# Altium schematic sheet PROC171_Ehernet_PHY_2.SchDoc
size 431 x 279 mm; Date: Not shown in title block; ApprovedBy: Not shown in title block; CheckedBy: Not shown in title block; Author: Not shown in title block; CompanyName: Not shown in title block; Engineer: Not shown in title block; Organization: Not shown in title block; Address1: Not shown in title block; Address2: Not shown in title block; Address3: Not shown in title block; Address4: Not shown in title block; DocumentNumber: 18; Revision: Use project parameter SCH_Rev; SheetNumber: 18; SheetTotal: 27; PageSetup: Record=PageOptions¦CenterHorizontal=True¦CenterVertical=True¦PrintScale=1.00¦XCorrection=1.00¦YCorrection=1.00¦PrintKind=0¦BorderSize=5000000¦LeftOffset=0¦BottomOffset=0¦Orientation=2¦PaperLength=1000¦PaperWidth=1000¦Scale=100¦PaperSource=15¦PrintQuality=600¦MediaType=1¦DitherType=10¦PaperKind=Letter¦PrintScaleMode=1
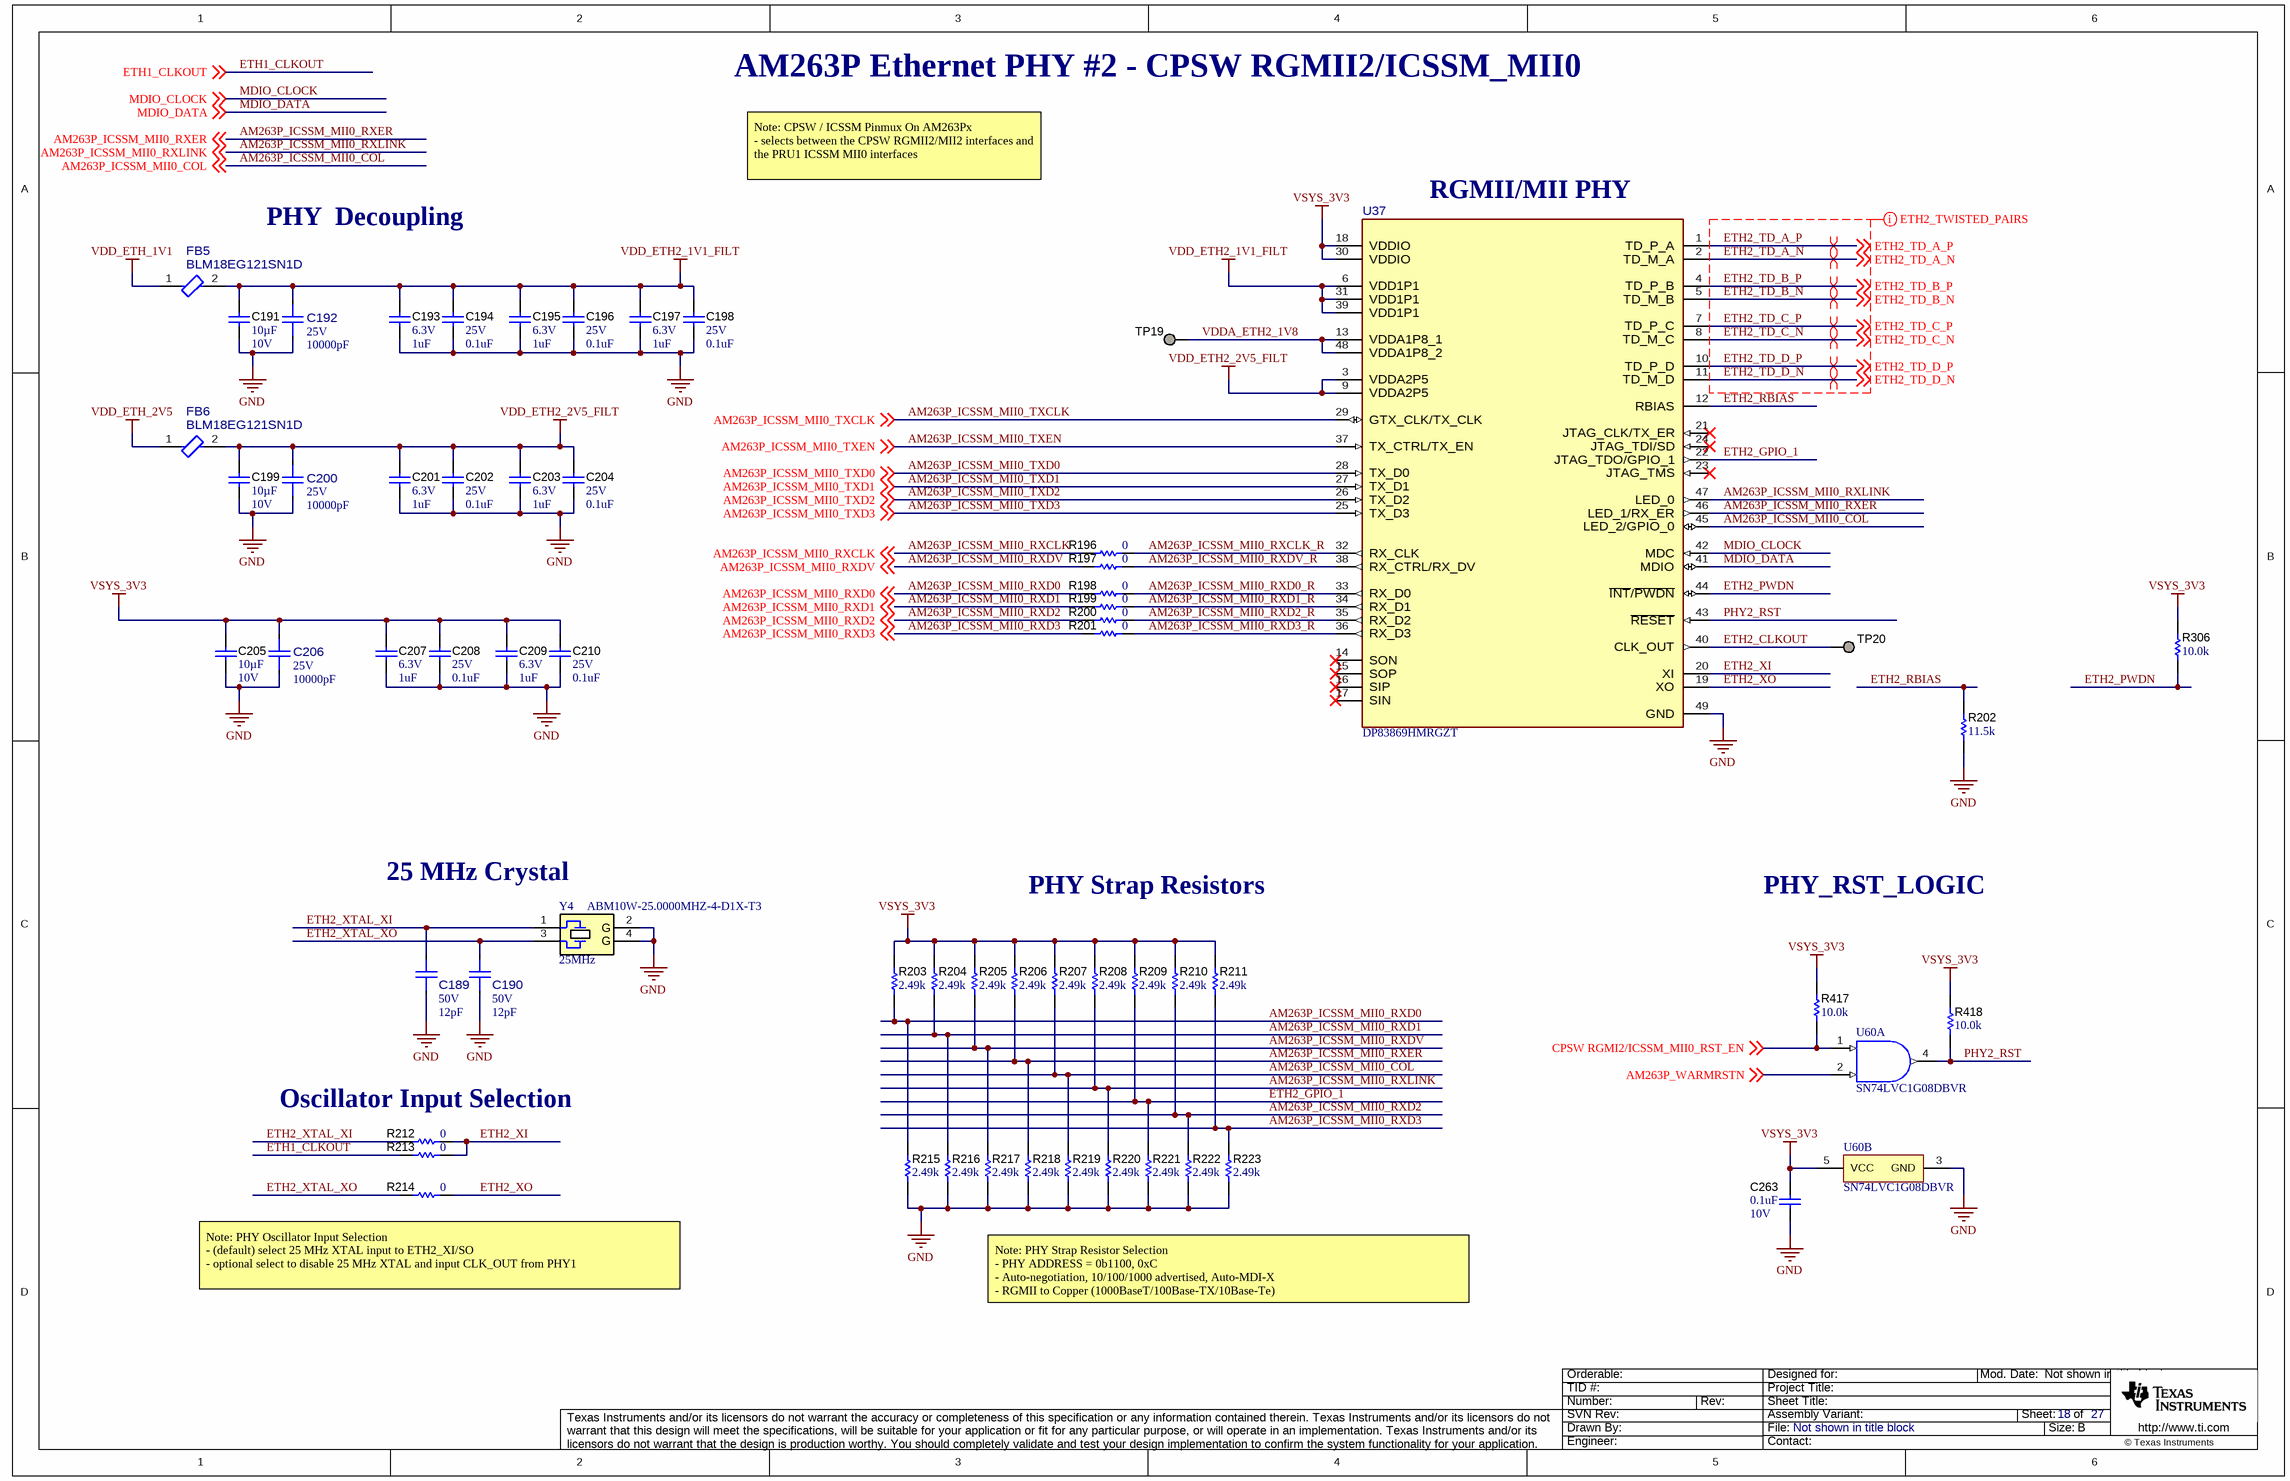
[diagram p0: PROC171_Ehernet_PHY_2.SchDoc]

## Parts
C189  VDC_V: 50V  ValueDisplayed: 12pF  [FP-GJM1555C1H120JB01D_0402-MFG]  (hidden comment: GJM1555C1H120JB01D)
C190  VDC_V: 50V  ValueDisplayed: 12pF  [FP-GJM1555C1H120JB01D_0402-MFG]  (hidden comment: GJM1555C1H120JB01D)
C191  Cap_F: 10µF  VDC_V: 10V  [0603]  (hidden comment: GRM188Z71A106MA73D)
C192  VDC_V: 25V  ValueDisplayed: 10000pF  [FP-GRM1555C1E103JE01D_0402-MFG]  (hidden comment: GRM1555C1E103JE01D)
C193  VDC_V: 6.3V  ValueDisplayed: 1uF  [0402]  (hidden comment: GRM155R70J105MA12D)
C194  VDC_V: 25V  ValueDisplayed: 0.1uF  [0402]  (hidden comment: GRM155R71E104KE14D)
C195  VDC_V: 6.3V  ValueDisplayed: 1uF  [0402]  (hidden comment: GRM155R70J105MA12D)
C196  VDC_V: 25V  ValueDisplayed: 0.1uF  [0402]  (hidden comment: GRM155R71E104KE14D)
C197  VDC_V: 6.3V  ValueDisplayed: 1uF  [0402]  (hidden comment: GRM155R70J105MA12D)
C198  VDC_V: 25V  ValueDisplayed: 0.1uF  [0402]  (hidden comment: GRM155R71E104KE14D)
C199  Cap_F: 10µF  VDC_V: 10V  [0603]  (hidden comment: GRM188Z71A106MA73D)
C200  VDC_V: 25V  ValueDisplayed: 10000pF  [FP-GRM1555C1E103JE01D_0402-MFG]  (hidden comment: GRM1555C1E103JE01D)
C201  VDC_V: 6.3V  ValueDisplayed: 1uF  [0402]  (hidden comment: GRM155R70J105MA12D)
C202  VDC_V: 25V  ValueDisplayed: 0.1uF  [0402]  (hidden comment: GRM155R71E104KE14D)
C203  VDC_V: 6.3V  ValueDisplayed: 1uF  [0402]  (hidden comment: GRM155R70J105MA12D)
C204  VDC_V: 25V  ValueDisplayed: 0.1uF  [0402]  (hidden comment: GRM155R71E104KE14D)
C205  Cap_F: 10µF  VDC_V: 10V  [0603]  (hidden comment: GRM188Z71A106MA73D)
C206  VDC_V: 25V  ValueDisplayed: 10000pF  [FP-GRM1555C1E103JE01D_0402-MFG]  (hidden comment: GRM1555C1E103JE01D)
C207  VDC_V: 6.3V  ValueDisplayed: 1uF  [0402]  (hidden comment: GRM155R70J105MA12D)
C208  VDC_V: 25V  ValueDisplayed: 0.1uF  [0402]  (hidden comment: GRM155R71E104KE14D)
C209  VDC_V: 6.3V  ValueDisplayed: 1uF  [0402]  (hidden comment: GRM155R70J105MA12D)
C210  VDC_V: 25V  ValueDisplayed: 0.1uF  [0402]  (hidden comment: GRM155R71E104KE14D)
C263  VDC_V: 10V  ValueDisplayed: 0.1uF  [0402]  (hidden comment: 885012105010)
FB5  BLM18EG121SN1D  [FP-BLM18EG121SN1D_0603-MFG]
FB6  BLM18EG121SN1D  [FP-BLM18EG121SN1D_0603-MFG]
R196  ValueDisplayed: 0  [0402]  (hidden comment: ERJ-2GE0R00X)
R197  ValueDisplayed: 0  [0402]  (hidden comment: ERJ-2GE0R00X)
R198  ValueDisplayed: 0  [0402]  (hidden comment: ERJ-2GE0R00X)
R199  ValueDisplayed: 0  [0402]  (hidden comment: ERJ-2GE0R00X)
R200  ValueDisplayed: 0  [0402]  (hidden comment: ERJ-2GE0R00X)
R201  ValueDisplayed: 0  [0402]  (hidden comment: ERJ-2GE0R00X)
R202  ValueDisplayed: 11.5k  [0402]  (hidden comment: ERJ-2RKF1152X)
R203  ValueDisplayed: 2.49k  [0402]  (hidden comment: CRCW04022K49FKED)
R204  ValueDisplayed: 2.49k  [0402]  (hidden comment: CRCW04022K49FKED)
R205  ValueDisplayed: 2.49k  [0402]  (hidden comment: CRCW04022K49FKED)
R206  ValueDisplayed: 2.49k  [0402]  (hidden comment: CRCW04022K49FKED)
R207  ValueDisplayed: 2.49k  [0402]  (hidden comment: CRCW04022K49FKED)
R208  ValueDisplayed: 2.49k  [0402]  (hidden comment: CRCW04022K49FKED)
R209  ValueDisplayed: 2.49k  [0402]  (hidden comment: CRCW04022K49FKED)
R210  ValueDisplayed: 2.49k  [0402]  (hidden comment: CRCW04022K49FKED)
R211  ValueDisplayed: 2.49k  [0402]  (hidden comment: CRCW04022K49FKED)
R212  ValueDisplayed: 0  [0402]  (hidden comment: ERJ-2GE0R00X)
R213  ValueDisplayed: 0  [0402]  (hidden comment: ERJ-2GE0R00X)
R214  ValueDisplayed: 0  [0402]  (hidden comment: ERJ-2GE0R00X)
R215  ValueDisplayed: 2.49k  [0402]  (hidden comment: CRCW04022K49FKED)
R216  ValueDisplayed: 2.49k  [0402]  (hidden comment: CRCW04022K49FKED)
R217  ValueDisplayed: 2.49k  [0402]  (hidden comment: CRCW04022K49FKED)
R218  ValueDisplayed: 2.49k  [0402]  (hidden comment: CRCW04022K49FKED)
R219  ValueDisplayed: 2.49k  [0402]  (hidden comment: CRCW04022K49FKED)
R220  ValueDisplayed: 2.49k  [0402]  (hidden comment: CRCW04022K49FKED)
R221  ValueDisplayed: 2.49k  [0402]  (hidden comment: CRCW04022K49FKED)
R222  ValueDisplayed: 2.49k  [0402]  (hidden comment: CRCW04022K49FKED)
R223  ValueDisplayed: 2.49k  [0402]  (hidden comment: CRCW04022K49FKED)
R306  ValueDisplayed: 10.0k  [0402]  (hidden comment: ERJ-2RKF1002X)
R417  ValueDisplayed: 10.0k  [0402]  (hidden comment: ERJ-2RKF1002X)
R418  ValueDisplayed: 10.0k  [0402L]  (hidden comment: CRCW040210K0FKED)
TP19  TESTPOINT  [TP_25MIL-SMT]  (value not drawn)  (no BOM)
TP20  TESTPOINT  [TP_25MIL-SMT]  (value not drawn)  (no BOM)
U37  DP83869HMRGZT  [RGZ0048B-MFG]
U60  SN74LVC1G08DBVR  [DBV0005A_N]  (parts A,B of 2)
Y4  Frequency_Fixed: 25MHz  [Abracon_ABM10W]  (hidden comment: ABM10W-25.0000MHZ-4-D1X-T3)

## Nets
GND: C189.1 C190.1 C191.2 C192.1 C193.2 C194.2 C195.2 C196.2 C197.2 C198.2 C199.2 C200.1 C201.2 C202.2 C203.2 C204.2 C205.2 C206.1 C207.2 C208.2 C209.2 C210.2 C263.2 R202.1 R215.1 R216.1 R217.1 R218.1 R219.1 R220.1 R221.1 R222.1 R223.1 U37.49(GND) U60.3(GND) Y4.2(GND) Y4.4(GND)
VDD_ETH2_1V1_FILT: C191.1 C192.2 C193.1 C194.1 C195.1 C196.1 C197.1 C198.1 FB5.2 U37.6(VDD1P1) U37.31(VDD1P1) U37.39(VDD1P1)
VDD_ETH2_2V5_FILT: C199.1 C200.2 C201.1 C202.1 C203.1 C204.1 FB6.2 U37.3(VDDA2P5) U37.9(VDDA2P5)
VDD_ETH_1V1: FB5.1
VDD_ETH_2V5: FB6.1
VSYS_3V3: C205.1 C206.2 C207.1 C208.1 C209.1 C210.1 C263.1 R203.2 R204.2 R205.2 R206.2 R207.2 R208.2 R209.2 R210.2 R211.2 R306.1 R417.1 R418.2 U37.18(VDDIO) U37.30(VDDIO) U60.5(VCC)
AM263P_ICSSM_MII0_COL: R207.1 R219.2 U37.45(LED_2/GPIO_0) ; off-sheet AM263P_ICSSM_MII0_COL
AM263P_ICSSM_MII0_RXCLK: R196.1 ; off-sheet AM263P_ICSSM_MII0_RXCLK
AM263P_ICSSM_MII0_RXCLK_R: R196.2 U37.32(RX_CLK)
AM263P_ICSSM_MII0_RXD0: R198.1 R203.1 R215.2 ; off-sheet AM263P_ICSSM_MII0_RXD0
AM263P_ICSSM_MII0_RXD0_R: R198.2 U37.33(RX_D0)
AM263P_ICSSM_MII0_RXD1: R199.1 R204.1 R216.2 ; off-sheet AM263P_ICSSM_MII0_RXD1
AM263P_ICSSM_MII0_RXD1_R: R199.2 U37.34(RX_D1)
AM263P_ICSSM_MII0_RXD2: R200.1 R210.1 R222.2 ; off-sheet AM263P_ICSSM_MII0_RXD2
AM263P_ICSSM_MII0_RXD2_R: R200.2 U37.35(RX_D2)
AM263P_ICSSM_MII0_RXD3: R201.1 R211.1 R223.2 ; off-sheet AM263P_ICSSM_MII0_RXD3
AM263P_ICSSM_MII0_RXD3_R: R201.2 U37.36(RX_D3)
AM263P_ICSSM_MII0_RXDV: R197.1 R205.1 R217.2 ; off-sheet AM263P_ICSSM_MII0_RXDV
AM263P_ICSSM_MII0_RXDV_R: R197.2 U37.38(RX_CTRL/RX_DV)
AM263P_ICSSM_MII0_RXER: R206.1 R218.2 U37.46(LED_1/RX_ER) ; off-sheet AM263P_ICSSM_MII0_RXER
AM263P_ICSSM_MII0_RXLINK: R208.1 R220.2 U37.47(LED_0) ; off-sheet AM263P_ICSSM_MII0_RXLINK
AM263P_ICSSM_MII0_TXCLK: U37.29(GTX_CLK/TX_CLK) ; off-sheet AM263P_ICSSM_MII0_TXCLK
AM263P_ICSSM_MII0_TXD0: U37.28(TX_D0) ; off-sheet AM263P_ICSSM_MII0_TXD0
AM263P_ICSSM_MII0_TXD1: U37.27(TX_D1) ; off-sheet AM263P_ICSSM_MII0_TXD1
AM263P_ICSSM_MII0_TXD2: U37.26(TX_D2) ; off-sheet AM263P_ICSSM_MII0_TXD2
AM263P_ICSSM_MII0_TXD3: U37.25(TX_D3) ; off-sheet AM263P_ICSSM_MII0_TXD3
AM263P_ICSSM_MII0_TXEN: U37.37(TX_CTRL/TX_EN) ; off-sheet AM263P_ICSSM_MII0_TXEN
AM263P_WARMRSTN: U60.2(B) ; off-sheet AM263P_WARMRSTN
CPSW RGMI2/ICSSM_MII0_RST_EN: R417.2 U60.1(A) ; off-sheet CPSW RGMI2/ICSSM_MII0_RST_EN
ETH1_CLKOUT: R213.1 ; off-sheet ETH1_CLKOUT
ETH2_CLKOUT: TP20.1 U37.40(CLK_OUT)
ETH2_GPIO_1: R209.1 R221.2 U37.22(JTAG_TDO/GPIO_1)
ETH2_PWDN: R306.2 U37.44(~{INT}/~{PWDN})
ETH2_RBIAS: R202.2 U37.12(RBIAS)
ETH2_TD_A_N: U37.2(TD_M_A) ; off-sheet ETH2_TD_A_N
ETH2_TD_A_P: U37.1(TD_P_A) ; off-sheet ETH2_TD_A_P
ETH2_TD_B_N: U37.5(TD_M_B) ; off-sheet ETH2_TD_B_N
ETH2_TD_B_P: U37.4(TD_P_B) ; off-sheet ETH2_TD_B_P
ETH2_TD_C_N: U37.8(TD_M_C) ; off-sheet ETH2_TD_C_N
ETH2_TD_C_P: U37.7(TD_P_C) ; off-sheet ETH2_TD_C_P
ETH2_TD_D_N: U37.11(TD_M_D) ; off-sheet ETH2_TD_D_N
ETH2_TD_D_P: U37.10(TD_P_D) ; off-sheet ETH2_TD_D_P
ETH2_XI: R212.2 R213.2 U37.20(XI)
ETH2_XO: R214.2 U37.19(XO)
ETH2_XTAL_XI: C189.2 R212.1 Y4.1
ETH2_XTAL_XO: C190.2 R214.1 Y4.3
MDIO_CLOCK: U37.42(MDC) ; off-sheet MDIO_CLOCK
MDIO_DATA: U37.41(MDIO) ; off-sheet MDIO_DATA
PHY2_RST: R418.1 U37.43(~{RESET}) U60.4(Y)
VDDA_ETH2_1V8: TP19.1 U37.13(VDDA1P8_1) U37.48(VDDA1P8_2)

Not connected (* = marked no-connect by the designer): U37 14(SON)* 15(SOP)* 16(SIP)* 17(SIN)* 21(JTAG_CLK/TX_ER)* 23(JTAG_TMS)* 24(JTAG_TDI/SD)*

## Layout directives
differential pair: ETH2_TD_A_N, ETH2_TD_A_P, ETH2_TD_B_N, ETH2_TD_B_P, ETH2_TD_C_N, ETH2_TD_C_P, ETH2_TD_D_N, ETH2_TD_D_P
mark named ETH2_TWISTED_PAIRS: ETH2_TD_A_N, ETH2_TD_A_P, ETH2_TD_B_N, ETH2_TD_B_P, ETH2_TD_C_N, ETH2_TD_C_P, ETH2_TD_D_N, ETH2_TD_D_P

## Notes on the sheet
- AM263P Ethernet PHY #2 - CPSW RGMII2/ICSSM_MII0
- PHY  Decoupling
- Note: CPSW / ICSSM Pinmux On AM263Px
  - selects between the CPSW RGMII2/MII2 interfaces and the PRU1 ICSSM MII0 interfaces
- (near U37) RGMII/MII PHY
- (near Y4) 25 MHz Crystal
- PHY Strap Resistors
- PHY_RST_LOGIC
- Oscillator Input Selection
- (near R214) Note: PHY Oscillator Input Selection
  - (default) select 25 MHz XTAL input to ETH2_XI/SO
  - optional select to disable 25 MHz XTAL and input CLK_OUT from PHY1
- Note: PHY Strap Resistor Selection
  - PHY ADDRESS = 0b1100, 0xC
  - Auto-negotiation, 10/100/1000 advertised, Auto-MDI-X
  - RGMII to Copper (1000BaseT/100Base-TX/10Base-Te)

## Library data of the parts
C189 C190 = CMP-0035228-1: Multi-Layer Ceramic Capacitor 12pF C0G  ±5% 0402 Paper T/R; Manufacturer: Murata; TempCo: 30ppm/°C; SizeZ_mm: 0.55mm; AEC Qualified: No
C191 C199 C205 = CMP-0007497-5: CAP, CERM, 10 uF, 10 V, +/- 20%, X7R, 0603; Manufacturer: MuRata; TaMin_C: -55°C; Polarized: N; SizeAreaWB_mm2: 4.68; Value1: Unknown; U/M: EA; Value: 10uF; TaMax_C: 125°C; SizeZ_mm: 1; SizeX_mm: 1.6; SizeY_mm: 0.8; SizeArea_mm2: 1.28; AEC Category: Q200
C192 C200 C206 = CMP-0035343-1: Chip Multilayer Ceramic Capacitors for General Purpose, 0402, 10000pF, C0G, 30ppm/°C, 5%, 25V; Manufacturer: Murata; Value: 10nF; SizeZ_mm: 0.65mm; AEC Qualified: No
C193 C195 C197 C201 C203 C207 C209 = CMP-0006624-2: CAP, CERM, 1 uF, 6.3 V, +/- 20%, X7R, 0402; Manufacturer: MuRata; TaMin_C: -55°C; Polarized: N; SizeAreaWB_mm2: 3; Value1: Unknown; U/M: EA; Value: 1uF; TaMax_C: 125°C; SizeZ_mm: 0.6; SizeX_mm: 1; SizeY_mm: 0.5; Cap_F: 1µF; AEC Category: Q200
C194 C196 C198 C202 C204 C208 C210 = CMP-0006659-2: CAP, CERM, 0.1 uF, 25 V, +/- 10%, X7R, 0402; Manufacturer: MuRata; TaMin_C: -55°C; Polarized: N; SizeAreaWB_mm2: 3; Value1: Unknown; U/M: EA; Value: 0.1uF; TaMax_C: 125°C; SizeZ_mm: 0.6; SizeX_mm: 1; SizeY_mm: 0.5; Cap_F: 100nF; AEC Category: Q200
C263 = CMP-0006221-2: CAP, CERM, 0.1 uF, 10 V, +/- 20%, X5R, 0402; Manufacturer: Wurth Elektronik; TaMin_C: -55°C; Polarized: N; SizeAreaWB_mm2: 3; Value1: Unknown; U/M: EA; Value: 0.1uF; TaMax_C: 85°C; SizeZ_mm: 0.6; SizeX_mm: 1; SizeY_mm: 0.5; Cap_F: 100nF; AEC Category: Q200
FB5 FB6 = CMP-0089199-1: 120 Ohms @ 100MHz 1  Ferrite Bead 0603 (1608 Metric) 2A 40mOhm; Manufacturer: Murata; DCR_ohm: 60m; AEC Qualified: No; Tolerance_%: 25%; SizeZ_mm: 0.95mm; Impedance At Frequency: 120Ω @ 100MHz
R196-R201 R212-R214 = CMP-0026992-3: RES, 0, 5%, 0.1 W, AEC-Q200 Grade 0, 0402; Manufacturer: Panasonic; Power_W: 100mW; TempCo: 600 ppm/C; Value_Code: 0000; Value: 0; EIA_Code: E24; SizeX_mm: 1; SizeY_mm: 0.5; SizeZ_mm: 0.6; Value2: 0.1W; AEC Qualified: Y; VDC_V: 50V; AEC Category: Q200; SizeAreaWB_mm2: 3
R202 = CMP-0082348-1: RES, 11.5 k, 1%, 0.1 W, AEC-Q200 Grade 0, 0402; Manufacturer: Panasonic; Value_Code: 11k5; SizeAreaWB_mm2: 3; SizeArea_mm2: 0.5; AEC Qualified: Y; AEC Category: Q200; Value: 11.5k; SizeZ_mm: 0.6; EIA_Code: E96; TempCo: 100 ppm/C; AEC Grade: 0; Power_W: 100mW; Value2: 0.1W; SizeX_mm: 1
R203-R211 R215-R223 = CMP-0026237-2: RES, 2.49 k, 1%, 0.063 W, AEC-Q200 Grade 0, 0402; Manufacturer: Vishay-Dale; Power_W: 63mW; TempCo: 100 ppm/C; Value_Code: 2k49; Value: 2.49k; EIA_Code: E96; SizeX_mm: 1; SizeY_mm: 0.5; SizeZ_mm: 0.6; Value2: 0.063W; AEC Qualified: Y; VDC_V: 50V; AEC Category: Q200; AEC Grade: 0
R306 R417 = CMP-0026658-1: RES, 10.0 k, 1%, 0.1 W, 0402; Manufacturer: Panasonic; Power_W: 100mW; TempCo: 100 ppm/C; Value_Code: 10k0; U/M: EA; Value: 10.0k; EIA_Code: E96; Res_ohm: 10k; SizeX_mm: 1; SizeY_mm: 0.5; SizeZ_mm: 0.6; Value2: 0.1W; VDC_V: 50V; AEC Category: Q200
R418 = CMP-0025958-3: RES, 10.0 k, 1%, 0.063 W, AEC-Q200 Grade 0, 0402; Manufacturer: Vishay-Dale; Power_W: 63mW; TempCo: 100 ppm/C; Value_Code: 10k0; Value: 10.0k; EIA_Code: E96; Res_ohm: 10k; SizeX_mm: 1; SizeY_mm: 0.5; SizeZ_mm: 0.6; Value2: 0.063W; AEC Qualified: Y; VDC_V: 50V; AEC Category: Q200; AEC Grade: 0
TP19 TP20 = CMP-0078143-3: TEST POINT.  No entry in BOM.
U37 = CMP-0091377-1: 1/1 Transceiver Ethernet 48-VQFN (7x7); Manufacturer: Texas Instruments; TaMin_C: -40°C; SizeZ_mm: 1mm; TaMax_C: +125°C; Max Supply Voltage: 3.45V; Number Of Channels: 1; AEC Qualified: No; Data Rate: 1000Mbits/s; Min Supply Voltage: 990mV; Simplex Duplex: Full-Duplex; Standoff Height: 0mm
U60 = CMP-0051588-2: Single 2-Input Positive-AND Gate, DBV0005A, LARGE T&R; Manufacturer: Texas Instruments; Logic: True; ICC @ Nom Voltage(Max)(mA): 0.01; VCC(Min)(V): 1.65; Bits(#): 1; Rating: Catalog; Schmitt Trigger: No; Voltage(Nom)(V): 1.8,2.5,3.3,5; Output Drive (IOL/IOH)(Max)(mA): 32/-32; Gate Type: AND; tpd @ Nom Voltage(Max)(ns): 4.5,6,4,5; VCC(Max)(V): 5.5; Output Type: CMOS; F @ Nom Voltage(Max)(Mhz): 150; Input Type: CMOS/TTL; Technology Family: LVC; AEC Category: Q200; AEC Qualified: N; CompType: IC
Y4 = CMP-0084811-1: Crystal, 25 MHz, 10 ppm, 4 pF, SMD; Manufacturer: Abracon Corporation; Load Capacitance: 4 pF; TaMax_C: 85°C; SizeY_mm: 2.5; SizeAreaWB_mm2: 10.5; AEC Category: Q200; Frequency Stability: 20 ppm; SizeX_mm: 2; SizeArea_mm2: 5; SizeZ_mm: 0.6; AEC Qualified: N; TaMin_C: -40°C; Frequency Tolerance: 10 ppm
